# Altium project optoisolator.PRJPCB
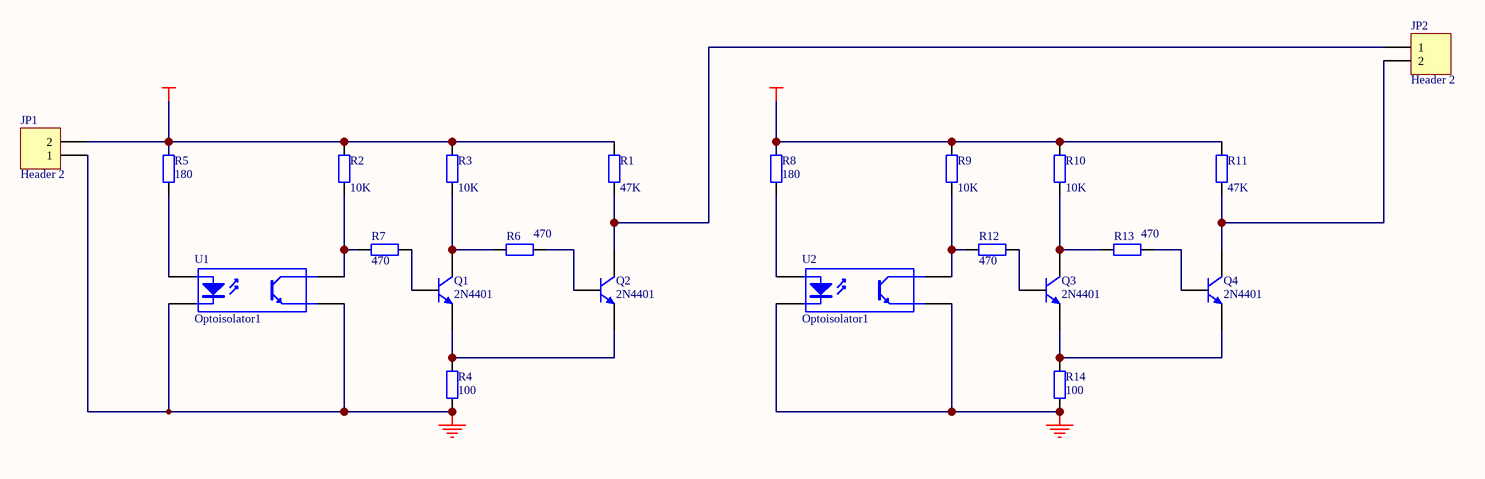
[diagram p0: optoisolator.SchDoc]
1 sheet, 22 parts. Net scope: global (net labels, ports and power ports of the same name join across sheets).
Board file: optoisolator.PCBDOC

## Sheet optoisolator.SchDoc
size B

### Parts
JP1  Header 2  [HDR1X2]
JP2  Header 2  [HDR1X2]
Q1  2N4401  [BCY-W3/D4.7]
Q2  2N4401  [BCY-W3/D4.7]
Q3  2N4401  [BCY-W3/D4.7]
Q4  2N4401  [BCY-W3/D4.7]
R1  value 47K  [AXIAL-0.4]  (hidden comment: Res2)
R2  10K  [AXIAL-0.4]
R3  value 10K  [AXIAL-0.4]  (hidden comment: Res2)
R4  value 100  [AXIAL-0.4]  (hidden comment: Res2)
R5  value 180  [AXIAL-0.4]  (hidden comment: Res2)
R6  value 470  [AXIAL-0.4]  (hidden comment: Res2)
R7  value 470  [AXIAL-0.4]  (hidden comment: Res2)
R8  value 180  [AXIAL-0.4]  (hidden comment: Res2)
R9  10K  [AXIAL-0.4]
R10  value 10K  [AXIAL-0.4]  (hidden comment: Res2)
R11  value 47K  [AXIAL-0.4]  (hidden comment: Res2)
R12  value 470  [AXIAL-0.4]  (hidden comment: Res2)
R13  value 470  [AXIAL-0.4]  (hidden comment: Res2)
R14  value 100  [AXIAL-0.4]  (hidden comment: Res2)
U1  Optoisolator1  [DIP-4]
U2  Optoisolator1  [DIP-4]

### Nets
+5V: JP1.2 R1.2 R2.2 R3.2 R5.2 R8.2 R9.2 R10.2 R11.2
GND: JP1.1 R4.1 R14.1 U1.2(K) U1.4(E) U2.2(K) U2.4(E)
NetJP2_1: JP2.1 Q2.3(C) R1.1
NetJP2_2: JP2.2 Q4.3(C) R11.1
NetQ1_1: Q1.1(E) Q2.1(E) R4.2
NetQ1_2: Q1.2(B) R7.2
NetQ1_3: Q1.3(C) R3.1 R6.1
NetQ2_2: Q2.2(B) R6.2
NetQ3_1: Q3.1(E) Q4.1(E) R14.2
NetQ3_2: Q3.2(B) R12.2
NetQ3_3: Q3.3(C) R10.1 R13.1
NetQ4_2: Q4.2(B) R13.2
NetR2_1: R2.1 R7.1 U1.3(C)
NetR5_1: R5.1 U1.1(A)
NetR8_1: R8.1 U2.1(A)
NetR9_1: R9.1 R12.1 U2.3(C)

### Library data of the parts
JP1 JP2 = Header 2: Header, 2-Pin; Manufacturer: Generic Components; Class I: Connector
Q1-Q4 = 2N4401: NPN General Purpose Amplifier; Manufacturer: Fairchild Semiconductor; Revision 1: 11-July-2000: SIM Model Added.; Revision 2: July-2002: Re-released for DXP Platform.; Package Information: Latest Revision: Sep-1998; Class I: Discrete; Class II: BJT - Low Power
R1-R14 = Res2: Resistor; Manufacturer: Generic Components; Class I: Passive
U1 U2 = Optoisolator1: Optoisolator; Manufacturer: Generic Components; Class I: Optoelectronic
